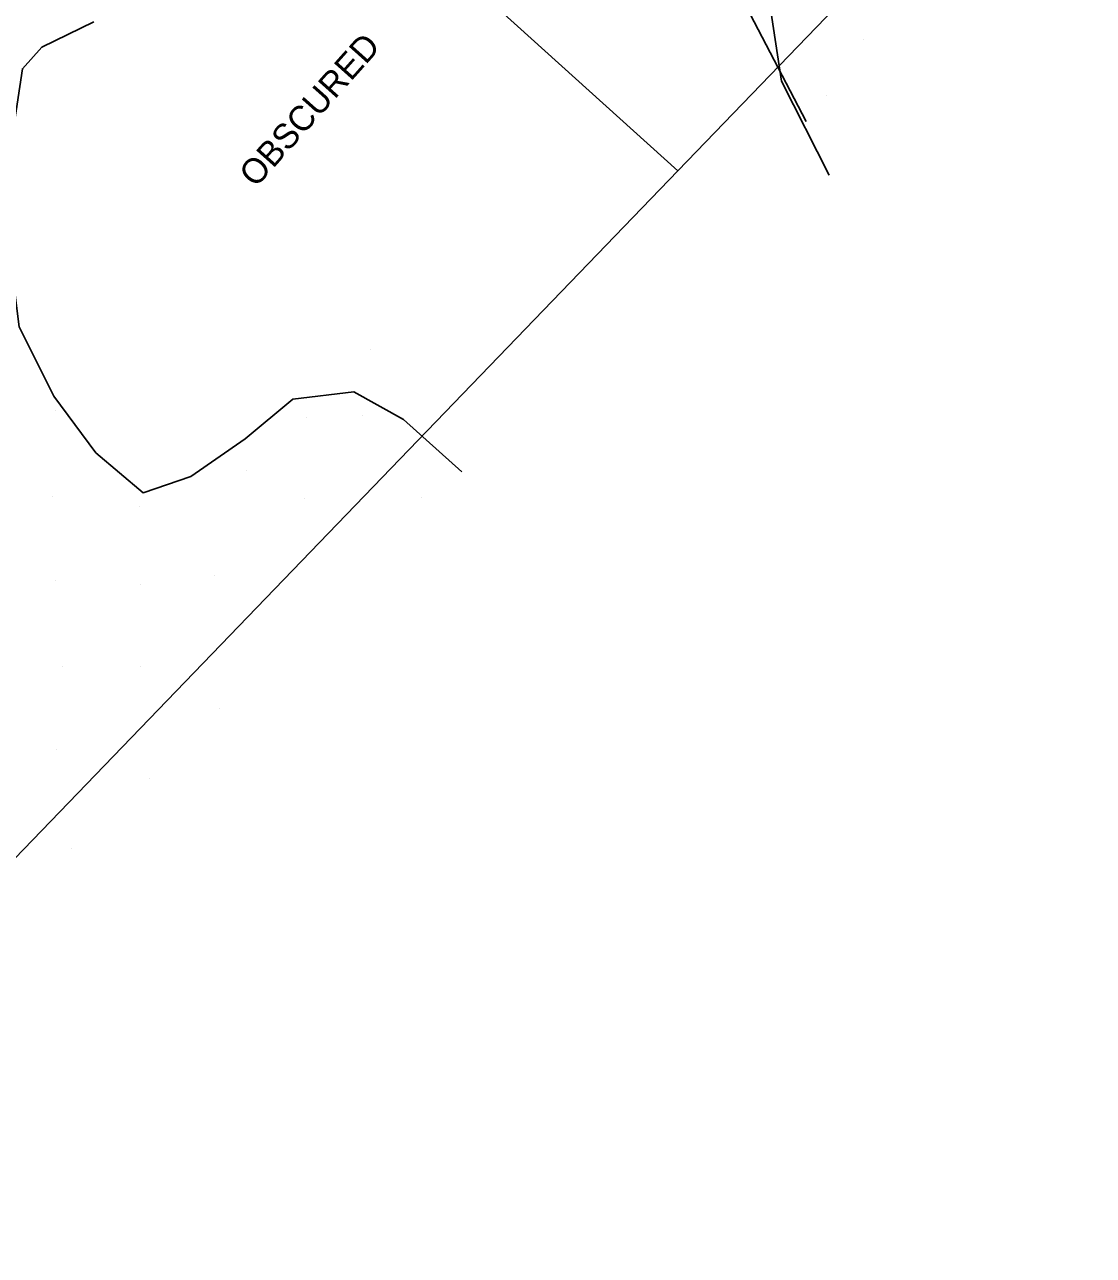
# Model space of a CAD drawing. Extents: x 1497074 to 1501343, y 481943 to 486114.
# Drawn here: x 1499408.8 to 1499665.7, y 485334 to 485629.8 of the extents above; entities that cross this region are included whole.
import ezdxf

# ---------------------------------------------------------------- set-up
doc = ezdxf.new("R2010")
doc.units = 0
for name, color, linetype in [('PH Exist DTM Boundary', 7, 'Continuous'), ('PH Exist DTM Breakline', 7, 'Continuous'), ('PH Exist DTM Obscure Area', 7, 'Continuous'), ('PH Exist DTM Obscure Area Text', 7, 'Continuous'), ('PH Exist DTM Point', 7, 'Continuous')]:
    doc.layers.add(name, color=color, linetype=linetype)

msp = doc.modelspace()

# ---------------------------------------------------------------- linework, layer by layer
at = {"layer": 'PH Exist DTM Boundary'}
for points in [[(1499194.3, 485929.74), (1499565.8, 485594.67), (1499665.72, 485698.27), (1499305.84, 486045.38)], [(1498846.5, 485569.16), (1499227.59, 485244.03), (1499565.8, 485594.67), (1499194.3, 485929.74)]]:
    msp.add_lwpolyline(points, close=True, dxfattribs=at)
at = {"layer": 'PH Exist DTM Breakline'}
msp.add_lwpolyline([(1499521.47, 485766.93), (1499524.44, 485763.56), (1499539.92, 485722.72), (1499556.12, 485684.28), (1499574.56, 485649.01), (1499596.64, 485606.52)], dxfattribs=at)
at = {"layer": 'PH Exist DTM Obscure Area'}
for points in [[(1499410.86, 485734.19), (1499420.97, 485745.81), (1499439.88, 485767.52), (1499482.12, 485813.42), (1499494.67, 485820.64), (1499509.05, 485817.66), (1499517.66, 485811.73), (1499544.37, 485760.38), (1499585.53, 485650.61), (1499590.74, 485616.18), (1499602.17, 485593.63)], [(1499513.88, 485522.34), (1499499.82, 485534.89), (1499487.92, 485541.54), (1499473.27, 485539.8), (1499461.8, 485530.28), (1499448.73, 485521.23), (1499437.28, 485517.32), (1499425.92, 485526.9), (1499415.81, 485540.51), (1499407.45, 485557.14), (1499404.7, 485578.88), (1499404.54, 485594.77), (1499408.26, 485619.21), (1499412.87, 485624.37), (1499425.41, 485630.45)]]:
    msp.add_lwpolyline(points, dxfattribs=at)
at = {"layer": 'PH Exist DTM Point'}
for p, q in [((1499610.51, 485626.27), (1499610.51, 485626.27)), ((1499601.45, 485612.83), (1499601.45, 485612.83)), ((1499491.93, 485551.84), (1499491.93, 485551.84)), ((1499416.3, 485537), (1499416.3, 485537)), ((1499476.62, 485535.4), (1499476.62, 485535.4)), ((1499489.94, 485535.98), (1499489.94, 485535.98)), ((1499462, 485522.59), (1499462, 485522.59)), ((1499415.51, 485516.39), (1499415.51, 485516.39)), ((1499476.14, 485515.83), (1499476.14, 485515.83)), ((1499504.09, 485516.19), (1499504.09, 485516.19)), ((1499436.34, 485513.95), (1499436.34, 485513.95)), ((1499416.27, 485496.18), (1499416.27, 485496.18)), ((1499436.69, 485495.27), (1499436.69, 485495.27)), ((1499454.43, 485497.37), (1499454.43, 485497.37)), ((1499417.82, 485475.54), (1499417.82, 485475.54)), ((1499436.54, 485475.47), (1499436.54, 485475.47)), ((1499455.52, 485465.43), (1499455.52, 485465.43)), ((1499416.42, 485455.57), (1499416.42, 485455.57)), ((1499438.71, 485448.54), (1499438.71, 485448.54)), ((1499420.04, 485431.88), (1499420.04, 485431.88))]:
    msp.add_line(p, q, dxfattribs=at)

# ---------------------------------------------------------------- texts
at = {"layer": 'PH Exist DTM Obscure Area Text'}
msp.add_text('OBSCURED', height=6, rotation=48.2276, dxfattribs=at).set_placement((1499464.32, 485590.43))

doc.saveas('drawing.dxf')
